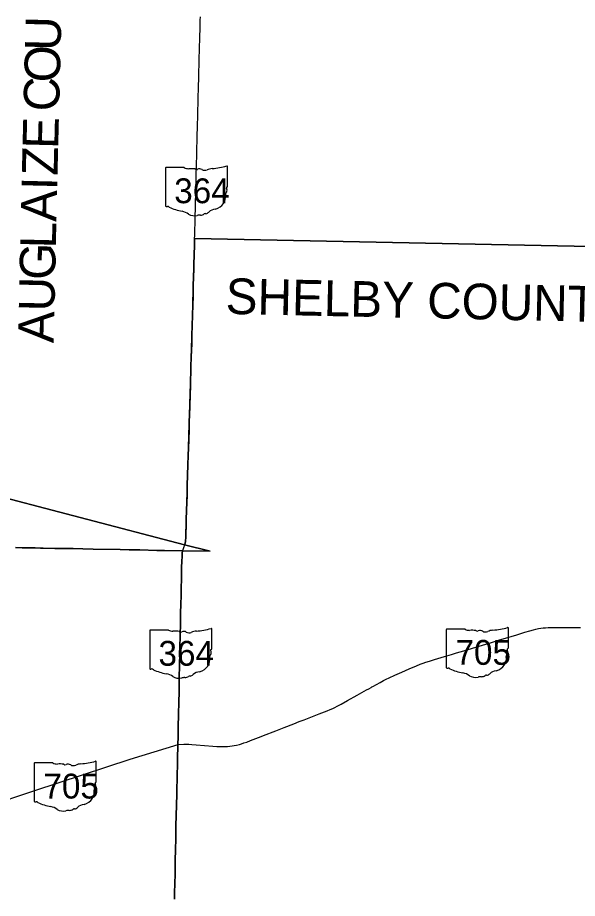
# Model space of a CAD drawing. Extents: x 0 to 34, y 0 to 22.
# Drawn here: x 4.2041 to 4.4563, y 18.5155 to 18.9124 of the extents above; entities that cross this region are included whole.
import ezdxf

# ---------------------------------------------------------------- set-up
doc = ezdxf.new("R2010")
doc.units = 0
for name, color, linetype in [('GM_X_County', 7, 'Continuous'), ('GM_X_County_Text', 7, 'Continuous'), ('GM_X_State_Location', 7, 'Continuous'), ('GM_X_State_Route', 7, 'Continuous'), ('GM_X_State_Shield', 7, 'Continuous')]:
    doc.layers.add(name, color=color, linetype=linetype)

msp = doc.modelspace()

# ---------------------------------------------------------------- linework, layer by layer
at = {"layer": 'GM_X_County'}
for points in [[(4.50934, 18.80852), (4.45476, 18.80929), (4.28383, 18.81284), (4.28376, 18.81015), (4.28363, 18.80509), (4.28353, 18.8014), (4.28346, 18.79887), (4.28336, 18.79555), (4.28322, 18.79147), (4.28311, 18.78722), (4.28297, 18.78216), (4.28288, 18.77884), (4.28272, 18.77283), (4.28264, 18.76993), (4.28263, 18.76941), (4.28252, 18.76551), (4.28231, 18.75934), (4.28218, 18.75507), (4.28191, 18.74643), (4.28177, 18.74232), (4.28161, 18.7372), (4.28148, 18.73325), (4.28139, 18.73041), (4.28129, 18.72693), (4.28114, 18.72197), (4.28104, 18.71855), (4.28094, 18.71501), (4.28081, 18.71085), (4.28053, 18.70157), (4.28041, 18.6972), (4.2802, 18.69035), (4.28008, 18.68608), (4.27999, 18.6835), (4.2799, 18.67959), (4.27983, 18.67775), (4.27976, 18.67685), (4.27968, 18.67622), (4.27956, 18.67559), (4.27932, 18.67472), (4.18503, 18.69938)], [(4.27471, 18.51513), (4.27478, 18.51824), (4.27489, 18.52188), (4.275, 18.52662), (4.27513, 18.53269), (4.27523, 18.53738), (4.27533, 18.54244), (4.27539, 18.54576), (4.27543, 18.54824), (4.27554, 18.55272), (4.27566, 18.55768), (4.27577, 18.56221), (4.27583, 18.56569), (4.2759, 18.56849), (4.27598, 18.57123), (4.27606, 18.5755), (4.27618, 18.57972), (4.27626, 18.58309), (4.27633, 18.58479), (4.27637, 18.58828), (4.27647, 18.59239), (4.2766, 18.59856), (4.27671, 18.60373), (4.2768, 18.60863), (4.27691, 18.61417), (4.27706, 18.62108), (4.27715, 18.62514), (4.27722, 18.62894), (4.27731, 18.63352), (4.27743, 18.6398), (4.27753, 18.64428), (4.2776, 18.64771), (4.27771, 18.6523), (4.27778, 18.65583), (4.27785, 18.65889), (4.27791, 18.66132), (4.27797, 18.66501), (4.27803, 18.66696), (4.27814, 18.67), (4.27828, 18.67136), (4.27834, 18.67176), (4.27841, 18.67203), (4.29087, 18.67197), (4.27932, 18.67472), (4.27956, 18.67559), (4.27968, 18.67622), (4.27976, 18.67685), (4.27983, 18.67775), (4.2799, 18.67959), (4.27999, 18.6835), (4.28008, 18.68608), (4.2802, 18.69035), (4.28041, 18.6972), (4.28053, 18.70157), (4.28081, 18.71085), (4.28094, 18.71501), (4.28104, 18.71855), (4.28114, 18.72197), (4.28129, 18.72693), (4.28139, 18.73041), (4.28148, 18.73325), (4.28161, 18.7372), (4.28177, 18.74232), (4.28191, 18.74643), (4.28218, 18.75507), (4.28231, 18.75934), (4.28252, 18.76551), (4.28263, 18.76941), (4.28264, 18.76993), (4.28272, 18.77283), (4.28288, 18.77884), (4.28297, 18.78216), (4.28311, 18.78722), (4.28322, 18.79147), (4.28336, 18.79555), (4.28346, 18.79887), (4.28353, 18.8014), (4.28363, 18.80509), (4.28376, 18.81015), (4.28383, 18.81284), (4.45476, 18.80929), (4.50934, 18.80852)], [(4.18503, 18.69938), (4.27932, 18.67472), (4.29087, 18.67197), (4.27841, 18.67203), (4.27024, 18.67222), (4.26683, 18.67229), (4.25917, 18.67245), (4.25428, 18.67254), (4.25027, 18.67263), (4.23811, 18.67286), (4.2334, 18.67295), (4.22908, 18.67305), (4.22086, 18.67319), (4.21555, 18.67331), (4.21433, 18.67333), (4.21203, 18.67337), (4.20619, 18.67346), (4.20308, 18.6735)], [(4.20308, 18.6735), (4.20619, 18.67346), (4.21203, 18.67337), (4.21433, 18.67333), (4.21555, 18.67331), (4.22086, 18.67319), (4.22908, 18.67305), (4.2334, 18.67295), (4.23811, 18.67286), (4.25027, 18.67263), (4.25428, 18.67254), (4.25917, 18.67245), (4.26683, 18.67229), (4.27024, 18.67222), (4.27841, 18.67203), (4.27834, 18.67176), (4.27828, 18.67136), (4.27814, 18.67), (4.27803, 18.66696), (4.27797, 18.66501), (4.27791, 18.66132), (4.27785, 18.65889), (4.27778, 18.65583), (4.27771, 18.6523), (4.2776, 18.64771), (4.27753, 18.64428), (4.27743, 18.6398), (4.27731, 18.63352), (4.27722, 18.62894), (4.27715, 18.62514), (4.27706, 18.62108), (4.27691, 18.61417), (4.2768, 18.60863), (4.27671, 18.60373), (4.2766, 18.59856), (4.27647, 18.59239), (4.27637, 18.58828), (4.27633, 18.58479), (4.27626, 18.58309), (4.27618, 18.57972), (4.27606, 18.5755), (4.27598, 18.57123), (4.2759, 18.56849), (4.27583, 18.56569), (4.27577, 18.56221), (4.27566, 18.55768), (4.27554, 18.55272), (4.27543, 18.54824), (4.27539, 18.54576), (4.27533, 18.54244), (4.27523, 18.53738), (4.27513, 18.53269), (4.275, 18.52662), (4.27489, 18.52188), (4.27478, 18.51824), (4.27471, 18.51513)]]:
    msp.add_lwpolyline(points, dxfattribs=at)
at = {"layer": 'GM_X_State_Route'}
for points in [[(4.28384, 18.81272), (4.28388, 18.8143), (4.28392, 18.81588), (4.28396, 18.81746), (4.284, 18.81904), (4.28404, 18.82062), (4.28408, 18.82221), (4.28412, 18.82379), (4.28416, 18.82537), (4.2842, 18.82695), (4.28423, 18.82853), (4.28427, 18.83011), (4.28431, 18.83169), (4.28435, 18.83328), (4.28439, 18.83486), (4.28443, 18.83644), (4.28447, 18.83802), (4.28451, 18.8396), (4.28455, 18.84118), (4.28459, 18.84277), (4.28463, 18.84435), (4.28467, 18.84593), (4.28471, 18.84751), (4.28475, 18.84909), (4.28478, 18.85067), (4.28482, 18.85225), (4.28486, 18.85384), (4.28488, 18.8547), (4.28491, 18.85556), (4.28495, 18.85714), (4.28499, 18.85872), (4.28503, 18.8603), (4.28507, 18.86188), (4.28511, 18.86346), (4.28516, 18.86504), (4.2852, 18.86663), (4.28524, 18.86821), (4.28528, 18.86979), (4.28532, 18.87137), (4.28536, 18.87295), (4.2854, 18.87453), (4.28544, 18.87612), (4.28549, 18.8777), (4.28553, 18.87928), (4.28557, 18.88086), (4.28561, 18.88244), (4.28565, 18.88402), (4.28569, 18.8856), (4.28573, 18.88719), (4.28578, 18.88877), (4.28582, 18.89035), (4.28586, 18.89193), (4.2859, 18.89351), (4.28594, 18.89509), (4.28598, 18.89668), (4.28601, 18.89759), (4.28603, 18.8985), (4.28608, 18.90008), (4.28612, 18.90166), (4.28616, 18.90324), (4.28621, 18.90482), (4.28625, 18.9064), (4.2863, 18.90799), (4.28634, 18.90957), (4.28639, 18.91115), (4.28643, 18.91273)], [(4.27934, 18.67467), (4.27955, 18.67539), (4.27966, 18.67582), (4.27974, 18.67625), (4.27978, 18.67663), (4.27982, 18.67724), (4.27984, 18.67795), (4.27989, 18.67954), (4.27993, 18.68112), (4.27998, 18.6827), (4.28003, 18.68428), (4.28008, 18.68586), (4.28012, 18.68744), (4.28017, 18.68903), (4.28022, 18.69061), (4.28027, 18.69219), (4.28031, 18.69377), (4.28036, 18.69535), (4.28041, 18.69693), (4.28045, 18.69852), (4.2805, 18.7001), (4.28055, 18.70164), (4.28059, 18.70318), (4.28064, 18.70476), (4.28069, 18.70634), (4.28073, 18.70792), (4.28078, 18.70951), (4.28083, 18.71109), (4.28087, 18.71267), (4.28092, 18.71425), (4.28097, 18.71583), (4.28102, 18.71741), (4.28106, 18.719), (4.28111, 18.72058), (4.28116, 18.72216), (4.2812, 18.72374), (4.28125, 18.72532), (4.28128, 18.72618), (4.2813, 18.72704), (4.28135, 18.72862), (4.2814, 18.7302), (4.28145, 18.73179), (4.2815, 18.73337), (4.28155, 18.73495), (4.2816, 18.73653), (4.28165, 18.73811), (4.28169, 18.73969), (4.28174, 18.74127), (4.28179, 18.74286), (4.28184, 18.74444), (4.28189, 18.74602), (4.28194, 18.7476), (4.28199, 18.74918), (4.28204, 18.75076), (4.28209, 18.75235), (4.28214, 18.75393), (4.28219, 18.75551), (4.28224, 18.75709), (4.28229, 18.75867), (4.28234, 18.76025), (4.28239, 18.76183), (4.28243, 18.76342), (4.28248, 18.765), (4.28253, 18.76658), (4.28258, 18.76816), (4.28261, 18.76901), (4.28264, 18.76986), (4.28268, 18.77144), (4.28272, 18.77302), (4.28277, 18.7746), (4.28281, 18.77618), (4.28286, 18.77776), (4.2829, 18.77935), (4.28295, 18.78093), (4.28299, 18.78251), (4.28303, 18.78409), (4.28308, 18.78567), (4.28312, 18.78725), (4.28317, 18.78884), (4.28321, 18.79042), (4.28324, 18.79142), (4.28326, 18.792), (4.2833, 18.79358), (4.28334, 18.79516), (4.28339, 18.79674), (4.28343, 18.79832), (4.28348, 18.79991), (4.28352, 18.80149), (4.28357, 18.80307), (4.28361, 18.80465), (4.28366, 18.80623), (4.2837, 18.80781), (4.28375, 18.8094), (4.28379, 18.81098), (4.28381, 18.81185), (4.28384, 18.81272)], [(4.27843, 18.67199), (4.27846, 18.67209), (4.27862, 18.67264), (4.27911, 18.67397), (4.27934, 18.67467)], [(4.27635, 18.58475), (4.27639, 18.58823), (4.27649, 18.59234), (4.27662, 18.59851), (4.27673, 18.60368), (4.27682, 18.60859), (4.27693, 18.61412), (4.27708, 18.62103), (4.27717, 18.62509), (4.27724, 18.62889), (4.27733, 18.63348), (4.27745, 18.63975), (4.27755, 18.64424), (4.27762, 18.64766), (4.27773, 18.65225), (4.2778, 18.65579), (4.27787, 18.65884), (4.27793, 18.66127), (4.27799, 18.66496), (4.27805, 18.66691), (4.27816, 18.66995), (4.2783, 18.67132), (4.27836, 18.67171), (4.27843, 18.67199)], [(4.27635, 18.58475), (4.27896, 18.5849), (4.28012, 18.58493), (4.28123, 18.58491), (4.28255, 18.58485), (4.2845, 18.5847), (4.29196, 18.5841), (4.2939, 18.58396), (4.29533, 18.5839), (4.29654, 18.58389), (4.29759, 18.58391), (4.29864, 18.58397), (4.29974, 18.58407), (4.30073, 18.5842), (4.30161, 18.58434), (4.30269, 18.58456), (4.30397, 18.58487), (4.30488, 18.58512), (4.30604, 18.58548), (4.30734, 18.58592), (4.30906, 18.58656), (4.31265, 18.58796), (4.31609, 18.5893), (4.31915, 18.5905), (4.32046, 18.59102), (4.32424, 18.5925), (4.32856, 18.59418), (4.33097, 18.59511), (4.33314, 18.59595), (4.33623, 18.59715), (4.33991, 18.5986), (4.34351, 18.59998), (4.34492, 18.60056), (4.34607, 18.60107), (4.34702, 18.60152), (4.34806, 18.60205), (4.34986, 18.60304), (4.35272, 18.60462), (4.3571, 18.60705), (4.3613, 18.60938), (4.36228, 18.60993), (4.36332, 18.61051), (4.36369, 18.61071), (4.36414, 18.61098), (4.36747, 18.61281), (4.36896, 18.61361), (4.37009, 18.61418), (4.37142, 18.61482), (4.37407, 18.61601), (4.37711, 18.61736), (4.38049, 18.61884), (4.38378, 18.62026), (4.38544, 18.62094), (4.38672, 18.62143), (4.38797, 18.62186), (4.38969, 18.62239), (4.39196, 18.62307), (4.3964, 18.62442), (4.39949, 18.62533), (4.40181, 18.62603), (4.40514, 18.62703), (4.41055, 18.62866), (4.41358, 18.62955), (4.41403, 18.62969), (4.41565, 18.63018), (4.41595, 18.63027), (4.41706, 18.63063), (4.42079, 18.63175), (4.42427, 18.63282), (4.42644, 18.63347), (4.42901, 18.63426), (4.43259, 18.63538), (4.43481, 18.63604), (4.43644, 18.63649), (4.43762, 18.63678), (4.43871, 18.63701), (4.43975, 18.63719), (4.4408, 18.63733), (4.44195, 18.63744), (4.44317, 18.63752), (4.4448, 18.63757), (4.44628, 18.63759), (4.44787, 18.63758), (4.44871, 18.63758), (4.45082, 18.63755), (4.45224, 18.63753), (4.45419, 18.63751), (4.45771, 18.63746)], [(4.14042, 18.54057), (4.14723, 18.54266), (4.19025, 18.55689), (4.21187, 18.56405), (4.25477, 18.57826), (4.27635, 18.58475)]]:
    msp.add_lwpolyline(points, dxfattribs=at)
at = {"layer": 'GM_X_State_Shield'}
for p, q in [((4.29866, 18.83633), (4.29866, 18.84522)), ((4.27069, 18.8445), (4.27069, 18.82752)), ((4.27916, 18.8448), (4.27097, 18.8448)), ((4.29866, 18.83633), (4.29866, 18.83633)), ((4.26359, 18.63607), (4.26359, 18.61909)), ((4.27206, 18.63637), (4.26387, 18.63637)), ((4.29156, 18.6279), (4.29156, 18.63679)), ((4.39721, 18.63649), (4.39721, 18.61951)), ((4.40568, 18.63678), (4.39749, 18.63678)), ((4.42518, 18.62832), (4.42518, 18.6372)), ((4.29156, 18.62791), (4.29156, 18.6279)), ((4.42518, 18.62832), (4.42518, 18.62832)), ((4.21154, 18.57624), (4.21154, 18.55926)), ((4.22, 18.57653), (4.21181, 18.57653)), ((4.23951, 18.56807), (4.23951, 18.57695)), ((4.23951, 18.56807), (4.23951, 18.56807))]:
    msp.add_line(p, q, dxfattribs=at)
for centre, major_axis, start_param, end_param in [((4.2887, 18.86795), (0.02966, 0), 4.814394, 5.042369), ((4.29835, 18.84525), (0.000311, 0), 6.141152, 7.989035), ((4.27101, 18.84454), (0.000324, 0), 1.712693, 3.28349), ((4.28111, 18.84677), (0.00314, 0), 4.042523, 4.731795), ((4.28215, 18.83526), (0.01128, 0), 1.404758, 1.657858), ((4.28471, 18.84463), (0.000907, 0), 3.836095, 5.185415), ((4.28605, 18.84267), (0.00189, 0), 0.950623, 2.079405), ((4.28848, 18.84536), (0.00227, 0), 4.081561, 5.145723), ((4.29248, 18.83961), (0.00597, 0), 1.699011, 2.107814), ((4.29978, 18.83261), (0.0021, 0), 2.387724, 3.262537), ((4.29859, 18.83568), (0.000482, 0), 1.883978, 3.671073), ((4.29553, 18.83456), (0.00289, 0), 5.934695, 6.695948), ((4.29833, 18.8363), (0.000333, 0), 5.05454, 6.418171), ((4.29036, 18.83148), (0.00742, 0), 5.101752, 6.440018), ((4.27102, 18.82748), (0.000327, 0), 3.00124, 4.508301), ((4.27107, 18.82922), (0.00249, 0), 4.665946, 4.897461), ((4.27158, 18.82654), (0.0009, 0), 0.519207, 1.627899), ((4.28293, 18.8418), (0.02142, 0), 4.195997, 4.488961), ((4.29349, 18.82275), (0.00406, 0), 1.647645, 2.488434), ((4.27655, 18.81989), (0.0067, 0), 0.823519, 1.323587), ((4.2838, 18.82646), (0.00425, 0), 4.026481, 4.996735), ((4.28625, 18.82058), (0.00349, 0), 1.495662, 1.94098), ((4.28656, 18.82518), (0.00227, 0), 4.691044, 5.507374), ((4.28861, 18.82354), (0.000638, 0), 1.147584, 2.315152), ((4.28834, 18.82587), (0.0024, 0), 4.937069, 5.64225), ((4.26391, 18.63611), (0.000324, 0), 1.712693, 3.28349), ((4.27401, 18.63834), (0.00314, 0), 4.042523, 4.731795), ((4.27505, 18.62683), (0.01128, 0), 1.404758, 1.657858), ((4.27761, 18.6362), (0.000907, 0), 3.836095, 5.185415), ((4.27894, 18.63424), (0.00189, 0), 0.950623, 2.079405), ((4.28138, 18.63693), (0.00227, 0), 4.081561, 5.145723), ((4.28538, 18.63118), (0.00597, 0), 1.699011, 2.107814), ((4.2816, 18.65952), (0.02966, 0), 4.814394, 5.042369), ((4.29125, 18.63682), (0.000311, 0), 6.141152, 7.989035), ((4.39753, 18.63653), (0.000324, 0), 1.712693, 3.28349), ((4.40763, 18.63875), (0.00314, 0), 4.042523, 4.731795), ((4.40867, 18.62725), (0.01128, 0), 1.404758, 1.657858), ((4.41123, 18.63661), (0.000907, 0), 3.836095, 5.185415), ((4.41256, 18.63465), (0.00189, 0), 0.950623, 2.079405), ((4.415, 18.63734), (0.00227, 0), 4.081561, 5.145723), ((4.419, 18.63159), (0.00597, 0), 1.699011, 2.107814), ((4.41522, 18.65994), (0.02966, 0), 4.814394, 5.042369), ((4.42487, 18.63724), (0.000311, 0), 6.141152, 7.989035), ((4.29149, 18.62725), (0.000482, 0), 1.883978, 3.671073), ((4.28842, 18.62613), (0.00289, 0), 5.934695, 6.695948), ((4.29123, 18.62787), (0.000333, 0), 5.05454, 6.418171), ((4.42511, 18.62767), (0.000482, 0), 1.883978, 3.671073), ((4.42204, 18.62654), (0.00289, 0), 5.934695, 6.695948), ((4.42485, 18.62828), (0.000333, 0), 5.05454, 6.418171), ((4.28326, 18.62305), (0.00742, 0), 5.101752, 6.440018), ((4.29268, 18.62418), (0.0021, 0), 2.387724, 3.262537), ((4.41688, 18.62347), (0.00742, 0), 5.101752, 6.440018), ((4.4263, 18.6246), (0.0021, 0), 2.387724, 3.262537), ((4.26391, 18.61905), (0.000327, 0), 3.00124, 4.508301), ((4.26396, 18.62079), (0.00249, 0), 4.665946, 4.897461), ((4.26447, 18.61811), (0.0009, 0), 0.519207, 1.627899), ((4.39753, 18.61947), (0.000327, 0), 3.00124, 4.508301), ((4.39758, 18.62121), (0.00249, 0), 4.665946, 4.897461), ((4.39809, 18.61853), (0.0009, 0), 0.519207, 1.627899), ((4.40945, 18.63379), (0.02142, 0), 4.195997, 4.488961), ((4.27583, 18.63337), (0.02142, 0), 4.195997, 4.488961), ((4.26945, 18.61146), (0.0067, 0), 0.823519, 1.323587), ((4.27669, 18.61803), (0.00425, 0), 4.026481, 4.996735), ((4.27915, 18.61215), (0.00349, 0), 1.495662, 1.94098), ((4.27946, 18.61675), (0.00227, 0), 4.691044, 5.507374), ((4.28151, 18.61511), (0.000638, 0), 1.147584, 2.315152), ((4.28124, 18.61744), (0.0024, 0), 4.937069, 5.64225), ((4.28639, 18.61432), (0.00406, 0), 1.647645, 2.488434), ((4.40307, 18.61187), (0.0067, 0), 0.823519, 1.323587), ((4.41031, 18.61844), (0.00425, 0), 4.026481, 4.996735), ((4.41277, 18.61257), (0.00349, 0), 1.495662, 1.94098), ((4.41308, 18.61717), (0.00227, 0), 4.691044, 5.507374), ((4.41513, 18.61552), (0.000638, 0), 1.147584, 2.315152), ((4.41486, 18.61786), (0.0024, 0), 4.937069, 5.64225), ((4.42001, 18.61474), (0.00406, 0), 1.647645, 2.488434), ((4.21186, 18.57628), (0.000324, 0), 1.712693, 3.28349), ((4.22195, 18.5785), (0.00314, 0), 4.042523, 4.731795), ((4.223, 18.567), (0.01128, 0), 1.404758, 1.657858), ((4.22556, 18.57637), (0.000907, 0), 3.836095, 5.185415), ((4.22689, 18.5744), (0.00189, 0), 0.950623, 2.079405), ((4.22932, 18.57709), (0.00227, 0), 4.081561, 5.145723), ((4.23333, 18.57135), (0.00597, 0), 1.699011, 2.107814), ((4.22954, 18.59969), (0.02966, 0), 4.814394, 5.042369), ((4.2392, 18.57699), (0.000311, 0), 6.141152, 7.989035), ((4.23944, 18.56742), (0.000482, 0), 1.883978, 3.671073), ((4.23637, 18.56629), (0.00289, 0), 5.934695, 6.695948), ((4.23918, 18.56803), (0.000333, 0), 5.05454, 6.418171), ((4.23121, 18.56322), (0.00742, 0), 5.101752, 6.440018), ((4.24062, 18.56435), (0.0021, 0), 2.387724, 3.262537), ((4.21186, 18.55922), (0.000327, 0), 3.00124, 4.508301), ((4.21191, 18.56096), (0.00249, 0), 4.665946, 4.897461), ((4.21242, 18.55828), (0.0009, 0), 0.519207, 1.627899), ((4.22378, 18.57354), (0.02142, 0), 4.195997, 4.488961), ((4.21739, 18.55163), (0.0067, 0), 0.823519, 1.323587), ((4.22464, 18.55819), (0.00425, 0), 4.026481, 4.996735), ((4.22741, 18.55692), (0.00227, 0), 4.691044, 5.507374), ((4.22946, 18.55528), (0.000638, 0), 1.147584, 2.315152), ((4.22919, 18.55761), (0.0024, 0), 4.937069, 5.64225), ((4.23433, 18.55449), (0.00406, 0), 1.647645, 2.488434), ((4.2271, 18.55232), (0.00349, 0), 1.495662, 1.94098)]:
    msp.add_ellipse(centre, major_axis=major_axis, ratio=0.8, start_param=start_param, end_param=end_param, dxfattribs=at)

# ---------------------------------------------------------------- texts
at = {"layer": 'GM_X_County_Text'}
for s, height, rotation, p in [('U', 0.01607, 88.5797, (4.22343, 18.89724)), ('O', 0.01607, 88.5716, (4.22308, 18.88303)), ('C', 0.01607, 88.562, (4.22275, 18.86995)), ('E', 0.01607, 88.5624, (4.22233, 18.85305)), ('Z', 0.01607, 88.5985, (4.22203, 18.84103)), ('I', 0.01607, 88.6509, (4.22188, 18.83446)), ('A', 0.01607, 88.6705, (4.22155, 18.82025)), ('L', 0.01607, 88.6994, (4.22127, 18.80823)), ('G', 0.01607, 88.7124, (4.22095, 18.79402)), ('U', 0.01607, 88.7184, (4.22064, 18.77981)), ('SHELBY COUNTY', 0.016074, 358.7591, (4.29768, 18.77887)), ('A', 0.01607, 88.7178, (4.22032, 18.7656))]:
    msp.add_text(s, height=height, rotation=rotation, dxfattribs=at).set_placement(p)
at = {"layer": 'GM_X_State_Location'}
for s, p in [('364', (4.27869, 18.83371)), ('364', (4.27159, 18.62528)), ('705', (4.40521, 18.6257)), ('705', (4.21953, 18.56545))]:
    msp.add_text(s, height=0.0000161, rotation=0, dxfattribs=at).set_placement(p)
for s, p in [('s', (4.28436, 18.83488)), ('r', (4.28436, 18.83488)), ('s', (4.41088, 18.62687)), ('r', (4.41088, 18.62687)), ('s', (4.27726, 18.62645)), ('r', (4.27726, 18.62645)), ('s', (4.22521, 18.56662)), ('r', (4.22521, 18.56662))]:
    msp.add_text(s, height=0.0000161, dxfattribs=at).set_placement(p)
at = {"layer": 'GM_X_State_Shield'}
for s, p in [('364', (4.27464, 18.82872)), ('364', (4.26754, 18.62029)), ('705', (4.40138, 18.6207)), ('705', (4.21571, 18.56045))]:
    msp.add_text(s, height=0.011189, dxfattribs=at).set_placement(p)

doc.saveas('drawing.dxf')
